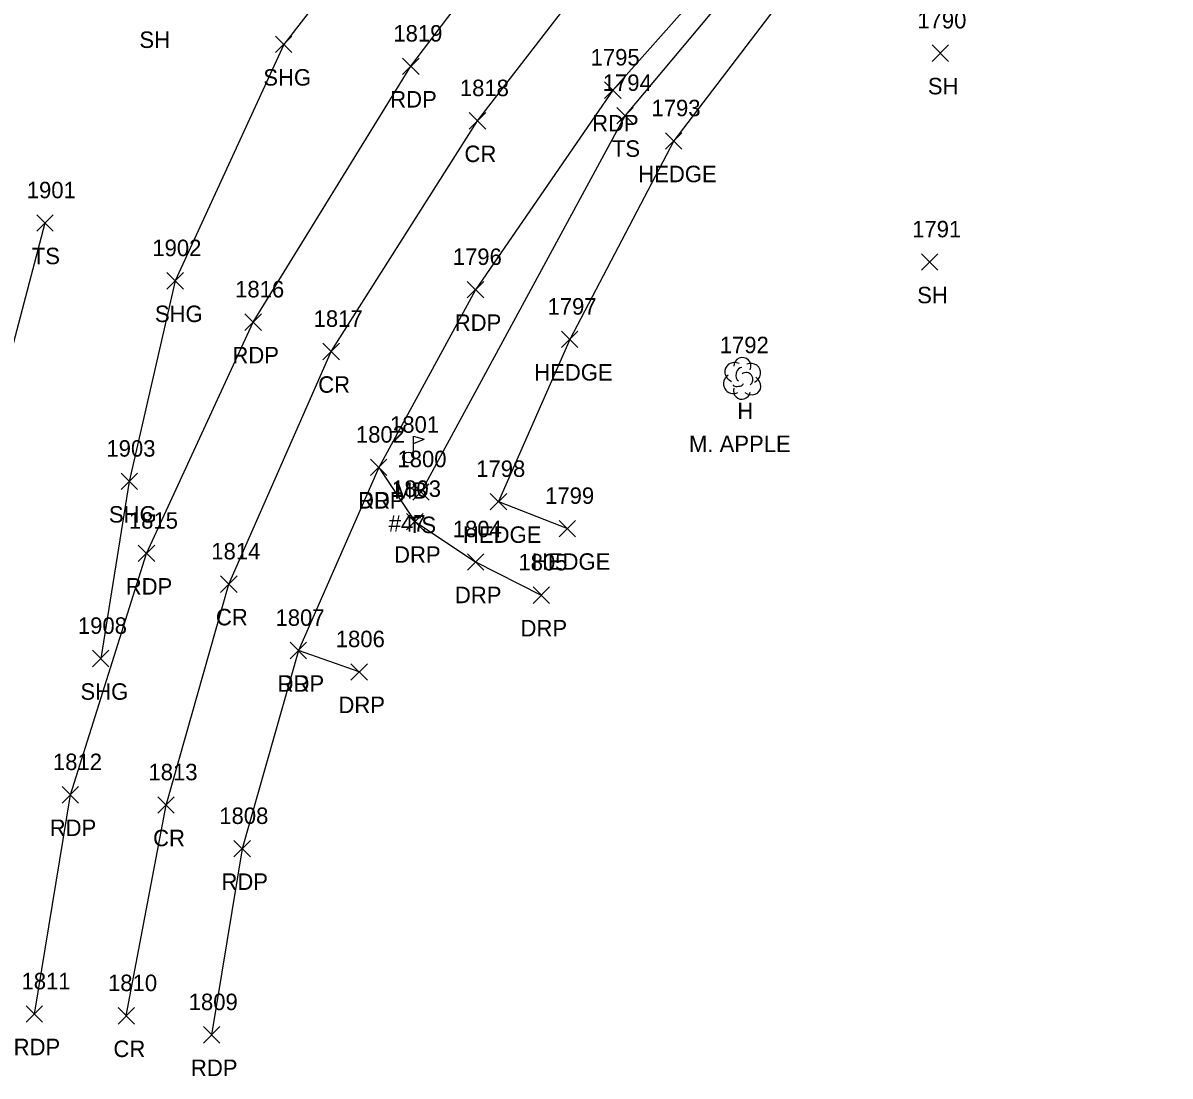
# Model space of a CAD drawing. Extents: x 1600395 to 1603269, y 874955 to 877143.
# Drawn here: x 1601763 to 1601902.1, y 874984.7 to 875112.5 of the extents above; entities that cross this region are included whole.
import ezdxf

# ---------------------------------------------------------------- set-up
doc = ezdxf.new("R2010")
doc.units = 0
for name, color, linetype in [('L_A', 7, 'Continuous'), ('L_C', 7, 'Continuous'), ('L_I', 7, 'Continuous'), ('L_TIC', 7, 'Continuous'), ('LAHR', 7, 'Continuous'), ('LELB', 7, 'Continuous'), ('LMB', 7, 'Continuous'), ('LTD', 7, 'Continuous'), ('P_A', 7, 'Continuous'), ('P_I', 7, 'Continuous'), ('P_TIC', 7, 'Continuous'), ('PET', 7, 'Continuous'), ('PRC', 7, 'Continuous'), ('PSU', 7, 'Continuous'), ('R_A', 7, 'Continuous'), ('R_I', 7, 'Continuous'), ('R_TIC', 7, 'Continuous'), ('RDP', 7, 'Continuous')]:
    doc.layers.add(name, color=color, linetype=linetype)

msp = doc.modelspace()

# ---------------------------------------------------------------- linework, layer by layer
at = {"layer": 'L_TIC'}
for points in [[(1601873.28, 875107.83), (1601875.28, 875109.83)], [(1601875.28, 875107.83), (1601873.28, 875109.83)], [(1601835.04, 875100.25), (1601837.04, 875102.25)], [(1601837.04, 875100.25), (1601835.04, 875102.25)], [(1601840.95, 875097.17), (1601842.95, 875099.17)], [(1601842.95, 875097.17), (1601840.95, 875099.17)], [(1601764.68, 875087.22), (1601766.68, 875089.22)], [(1601766.68, 875087.22), (1601764.68, 875089.22)], [(1601872, 875082.48), (1601874, 875084.48)], [(1601874, 875082.48), (1601872, 875084.48)], [(1601828.33, 875073.1), (1601830.33, 875075.1)], [(1601830.33, 875073.1), (1601828.33, 875075.1)], [(1601810.3, 875054.59), (1601812.3, 875056.59)], [(1601812.3, 875054.59), (1601810.3, 875056.59)], [(1601819.69, 875053.41), (1601821.69, 875055.41)], [(1601821.69, 875053.41), (1601819.69, 875055.41)], [(1601828.05, 875050.14), (1601830.05, 875052.14)], [(1601830.05, 875050.14), (1601828.05, 875052.14)]]:
    msp.add_lwpolyline(points, dxfattribs=at)
at = {"layer": 'LAHR'}
msp.add_lwpolyline([(1601867.51, 875131.71), (1601841.95, 875098.17), (1601829.33, 875074.1), (1601820.69, 875054.41), (1601829.05, 875051.14)], dxfattribs=at)
at = {"layer": 'LELB'}
for points in [[(1602178.37, 875249.14), (1602177.41, 875259.28), (1602168.51, 875260), (1602131.87, 875260.27), (1602108.92, 875258.18), (1602075.25, 875254.52), (1602028.81, 875250.19), (1601991.89, 875244.7), (1601984.63, 875238.19), (1601978.7, 875235.57), (1601960.11, 875224.3), (1601939.91, 875209.73), (1601913.86, 875184.56), (1601890.29, 875159.09), (1601878.53, 875149.19), (1601876.37, 875148.08), (1601869.76, 875141.55), (1601836.04, 875101.25), (1601811.3, 875055.59)], [(1601765.68, 875088.22), (1601759.88, 875066.31), (1601757.66, 875057.62), (1601751.31, 875023.09), (1601756.38, 874993.66)]]:
    msp.add_lwpolyline(points, dxfattribs=at)
at = {"layer": 'LMB'}
for p, q in [((1601810.4, 875062.37), (1601811.69, 875061.99)), ((1601810.4, 875059.78), (1601810.4, 875062.37)), ((1601810.4, 875061.47), (1601811.68, 875061.98)), ((1601809.75, 875059.77), (1601809.75, 875059.77))]:
    msp.add_line(p, q, dxfattribs=at)
msp.add_circle((1601809.75, 875059.77), 0.656, dxfattribs=at)
at = {"layer": 'LTD'}
msp.add_line((1601850.23, 875069.42), (1601850.23, 875069.42), dxfattribs=at)
msp.add_line((1601850.23, 875069.42), (1601850.23, 875069.42), dxfattribs=at)
msp.add_arc((1601850.27, 875070.85), 1.05, 335.5272, 180.9563, dxfattribs=at)
for centre, major_axis, ratio, start_param, end_param in [((1601849.43, 875070.09), (1.21, -0.51), 0.895232, 1.570796, 4.712389), ((1601851.27, 875070), (-1.14, -0.48), 0.949671, 1.570796, 4.712389), ((1601849.14, 875068.71), (0.58, -1.04), 0.959034, 3.141593, 6.283185), ((1601850.02, 875069.88), (-0.208, -0.792), 0.645439, 3.141593, 6.283185), ((1601850.73, 875069.25), (-0.5, 0.667), 0.989748, 3.141593, 6.283185), ((1601851.23, 875068.59), (-1.09, 0.79), 0.841452, 1.570796, 4.712389), ((1601850.23, 875067.92), (0.26, 1.06), 0.942809, 1.570796, 4.712389), ((1601849.77, 875068.67), (-0.625, -0.083), 0.423636, 0, 3.141593)]:
    msp.add_ellipse(centre, major_axis=major_axis, ratio=ratio, start_param=start_param, end_param=end_param, dxfattribs=at)
at = {"layer": 'P_TIC'}
for points in [[(1601793.64, 875108.89), (1601795.64, 875110.89)], [(1601795.64, 875108.89), (1601793.64, 875110.89)], [(1601809.07, 875106.23), (1601811.07, 875108.23)], [(1601811.07, 875106.23), (1601809.07, 875108.23)], [(1601833.56, 875103.33), (1601835.56, 875105.33)], [(1601835.56, 875103.33), (1601833.56, 875105.33)], [(1601817.14, 875099.61), (1601819.14, 875101.61)], [(1601819.14, 875099.61), (1601817.14, 875101.61)], [(1601780.48, 875080.2), (1601782.48, 875082.2)], [(1601782.48, 875080.2), (1601780.48, 875082.2)], [(1601816.9, 875079.13), (1601818.9, 875081.13)], [(1601818.9, 875079.13), (1601816.9, 875081.13)], [(1601789.93, 875075.19), (1601791.93, 875077.19)], [(1601791.93, 875075.19), (1601789.93, 875077.19)], [(1601799.4, 875071.62), (1601801.4, 875073.62)], [(1601801.4, 875071.62), (1601799.4, 875073.62)], [(1601805.17, 875057.57), (1601807.17, 875059.57)], [(1601807.17, 875057.57), (1601805.17, 875059.57)], [(1601774.91, 875055.87), (1601776.91, 875057.87)], [(1601776.91, 875055.87), (1601774.91, 875057.87)], [(1601777, 875047.13), (1601779, 875049.13)], [(1601779, 875047.13), (1601777, 875049.13)], [(1601786.98, 875043.4), (1601788.98, 875045.4)], [(1601788.98, 875043.4), (1601786.98, 875045.4)], [(1601771.45, 875034.37), (1601773.45, 875036.37)], [(1601773.45, 875034.37), (1601771.45, 875036.37)], [(1601795.42, 875035.34), (1601797.42, 875037.34)], [(1601797.42, 875035.34), (1601795.42, 875037.34)], [(1601767.77, 875017.84), (1601769.77, 875019.84)], [(1601769.77, 875017.84), (1601767.77, 875019.84)], [(1601779.37, 875016.6), (1601781.37, 875018.6)], [(1601781.37, 875016.6), (1601779.37, 875018.6)], [(1601788.6, 875011.3), (1601790.6, 875013.3)], [(1601790.6, 875011.3), (1601788.6, 875013.3)], [(1601763.4, 874991.24), (1601765.4, 874993.24)], [(1601765.4, 874991.24), (1601763.4, 874993.24)], [(1601774.55, 874991.02), (1601776.55, 874993.02)], [(1601776.55, 874991.02), (1601774.55, 874993.02)], [(1601784.9, 874988.71), (1601786.9, 874990.71)], [(1601786.9, 874988.71), (1601784.9, 874990.71)]]:
    msp.add_lwpolyline(points, dxfattribs=at)
at = {"layer": 'PET'}
for points in [[(1601981.36, 875249.81), (1601972.89, 875242.44), (1601955.9, 875227.49), (1601938.25, 875211.84), (1601911.53, 875186.46), (1601887.52, 875162.64), (1601873.65, 875148.4), (1601834.56, 875104.33), (1601817.9, 875080.13), (1601806.17, 875058.57), (1601796.42, 875036.34), (1601789.6, 875012.3), (1601785.9, 874989.71)], [(1601764.4, 874992.24), (1601768.77, 875018.84), (1601778, 875048.13), (1601790.93, 875076.19), (1601810.07, 875107.23), (1601828.65, 875131.77), (1601847.51, 875153.36), (1601863.92, 875170.53), (1601881.76, 875188.71), (1601893.9, 875201.56), (1601897.71, 875209.52), (1601897.17, 875214.83), (1601896.08, 875222.12), (1601893.32, 875227.87), (1601887.41, 875234.65), (1601882.14, 875236.79)]]:
    msp.add_lwpolyline(points, dxfattribs=at)
at = {"layer": 'PRC'}
msp.add_lwpolyline([(1601775.55, 874992.02), (1601780.37, 875017.6), (1601787.98, 875044.4), (1601800.4, 875072.62), (1601818.14, 875100.61), (1601837.01, 875125.1), (1601855.24, 875145.38), (1601891.25, 875181.43), (1601904.02, 875195.8), (1601914.31, 875205.65), (1601919.01, 875213.2), (1601928.75, 875226.86), (1601931, 875235.48), (1601931.43, 875243.62)], dxfattribs=at)
at = {"layer": 'PSU'}
msp.add_lwpolyline([(1601863.92, 875170.53), (1601833.6, 875145.14), (1601813.05, 875133.63), (1601794.64, 875109.89), (1601781.48, 875081.2), (1601775.91, 875056.87), (1601772.45, 875035.37)], dxfattribs=at)
at = {"layer": 'R_TIC'}
for points in [[(1601805.17, 875057.57), (1601807.17, 875059.57)], [(1601807.17, 875057.57), (1601805.17, 875059.57)], [(1601809.54, 875050.99), (1601811.54, 875052.99)], [(1601811.54, 875050.99), (1601809.54, 875052.99)], [(1601816.92, 875046.09), (1601818.92, 875048.09)], [(1601818.92, 875046.09), (1601816.92, 875048.09)], [(1601824.88, 875042.06), (1601826.88, 875044.06)], [(1601826.88, 875042.06), (1601824.88, 875044.06)], [(1601795.42, 875035.34), (1601797.42, 875037.34)], [(1601797.42, 875035.34), (1601795.42, 875037.34)], [(1601802.79, 875032.75), (1601804.79, 875034.75)], [(1601804.79, 875032.75), (1601802.79, 875034.75)]]:
    msp.add_lwpolyline(points, dxfattribs=at)
at = {"layer": 'RDP'}
for points in [[(1601806.17, 875058.57), (1601810.54, 875051.99), (1601817.92, 875047.09), (1601825.88, 875043.06)], [(1601803.79, 875033.75), (1601796.42, 875036.34)]]:
    msp.add_lwpolyline(points, dxfattribs=at)

# ---------------------------------------------------------------- texts
at = {"layer": 'L_A'}
for s, p in [('SH', (1601777.14, 875109.46)), ('SH', (1601872.77, 875103.83)), ('TS', (1601834.45, 875096.25)), ('HEDGE', (1601837.65, 875093.17)), ('TS', (1601764.09, 875083.22)), ('SH', (1601871.48, 875078.48)), ('HEDGE', (1601825.03, 875069.1)), ('H', (1601849.66, 875064.42)), ('MB', (1601808.05, 875054.77)), ('TS', (1601809.71, 875050.59)), ('HEDGE', (1601816.39, 875049.41)), ('HEDGE', (1601824.75, 875046.14))]:
    msp.add_text(s, height=2, dxfattribs=at).set_placement(p)
at = {"layer": 'L_C'}
for s, p in [('M. APPLE', (1601843.8, 875060.42)), ('#47', (1601807.38, 875050.77))]:
    msp.add_text(s, height=2, dxfattribs=at).set_placement(p)
at = {"layer": 'L_I'}
for s, p in [('1790', (1601871.5, 875111.83)), ('1794', (1601833.34, 875104.25)), ('1793', (1601839.25, 875101.17)), ('1901', (1601763.48, 875091.22)), ('1791', (1601870.87, 875086.48)), ('1797', (1601826.64, 875077.1)), ('1792', (1601847.53, 875072.42)), ('1801', (1601807.54, 875062.77)), ('1800', (1601808.44, 875058.59)), ('1798', (1601817.99, 875057.41)), ('1799', (1601826.35, 875054.14))]:
    msp.add_text(s, height=2, dxfattribs=at).set_placement(p)
at = {"layer": 'P_A'}
for s, p in [('SHG', (1601792.17, 875104.89)), ('RDP', (1601807.56, 875102.23)), ('RDP', (1601832.05, 875099.33)), ('CR', (1601816.57, 875095.61)), ('SHG', (1601779.02, 875076.2)), ('RDP', (1601815.39, 875075.13)), ('RDP', (1601788.42, 875071.19)), ('CR', (1601798.83, 875067.62)), ('RDP', (1601803.66, 875053.57)), ('SHG', (1601773.44, 875051.87)), ('RDP', (1601775.48, 875043.13)), ('CR', (1601786.42, 875039.4)), ('RDP', (1601793.9, 875031.34)), ('SHG', (1601769.99, 875030.37)), ('RDP', (1601766.26, 875013.84)), ('CR', (1601778.8, 875012.6)), ('RDP', (1601787.09, 875007.3)), ('RDP', (1601761.89, 874987.24)), ('CR', (1601773.99, 874987.02)), ('RDP', (1601783.39, 874984.71))]:
    msp.add_text(s, height=2, dxfattribs=at).set_placement(p)
at = {"layer": 'P_I'}
for s, p in [('1819', (1601807.94, 875110.23)), ('1795', (1601831.87, 875107.33)), ('1818', (1601816.01, 875103.61)), ('1902', (1601778.71, 875084.2)), ('1796', (1601815.15, 875083.13)), ('1816', (1601788.75, 875079.19)), ('1817', (1601798.27, 875075.62)), ('1802', (1601803.4, 875061.57)), ('1903', (1601773.14, 875059.87)), ('1815', (1601775.87, 875051.13)), ('1814', (1601785.86, 875047.4)), ('1908', (1601769.68, 875038.37)), ('1807', (1601793.65, 875039.34)), ('1812', (1601766.65, 875021.84)), ('1813', (1601778.24, 875020.6)), ('1808', (1601786.83, 875015.3)), ('1811', (1601762.84, 874995.24)), ('1810', (1601773.34, 874995.02)), ('1809', (1601783.12, 874992.71))]:
    msp.add_text(s, height=2, dxfattribs=at).set_placement(p)
at = {"layer": 'R_A'}
for p in [(1601803.66, 875053.57), (1601808.03, 875046.99), (1601815.41, 875042.09), (1601823.37, 875038.06), (1601793.9, 875031.34), (1601801.28, 875028.75)]:
    msp.add_text('DRP', height=2, dxfattribs=at).set_placement(p)
at = {"layer": 'R_I'}
for s, p in [('1802', (1601803.4, 875061.57)), ('1803', (1601807.77, 875054.99)), ('1804', (1601815.15, 875050.09)), ('1805', (1601823.11, 875046.06)), ('1807', (1601793.65, 875039.34)), ('1806', (1601800.96, 875036.75))]:
    msp.add_text(s, height=2, dxfattribs=at).set_placement(p)

doc.saveas('drawing.dxf')
